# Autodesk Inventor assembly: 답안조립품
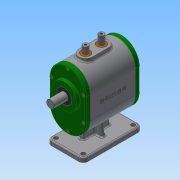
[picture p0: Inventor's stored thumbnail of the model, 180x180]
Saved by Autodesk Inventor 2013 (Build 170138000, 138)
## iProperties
Created: 2018-10
Part Number: 답안조립품
Document SubType Name: Assembly
Designer: Administrator
Author: Administrator
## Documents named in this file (15)
- C:\Users\Administrator\Desktop\381007V1015\답안조립품.iam
- C:\Users\Administrator\Desktop\381007V1015\본체.ipt
- C:\Users\Administrator\Desktop\381007V1015\뒤커버.ipt
- C:\Users\Administrator\Desktop\381007V1015\메인축.ipt
- C:\Users\Administrator\Desktop\381007V1015\베어링 608.ipt
- C:\Users\Administrator\Desktop\381007V1015\베어링 6003.ipt
- C:\Users\Administrator\Desktop\381007V1015\볼트 M4.ipt
- C:\Users\Administrator\Desktop\381007V1015\부시.ipt
- C:\Users\Administrator\Desktop\381007V1015\서브축.ipt
- C:\Users\Administrator\Desktop\381007V1015\슬라이더.ipt
- C:\Users\Administrator\Desktop\381007V1015\앞커버.ipt
- C:\Users\Administrator\Desktop\381007V1015\오일실 8 22 7.ipt
- C:\Users\Administrator\Desktop\381007V1015\오일실 17 32 8.ipt
- C:\Users\Administrator\Desktop\381007V1015\가변스프링.ipt
- C:\Users\Administrator\Desktop\381007V1015\가변스프링..ipt
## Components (2 placed, 2 different names)
1. 가변스프링:1
2. 가변스프링.:1
